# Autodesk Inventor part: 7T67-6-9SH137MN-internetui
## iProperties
Created: 2010-02
Part Number: 7T67-6-9SH137MN-internetui
Document SubType Name: Modeling
Designer: Darius
Author: Darius
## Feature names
1. Base1
